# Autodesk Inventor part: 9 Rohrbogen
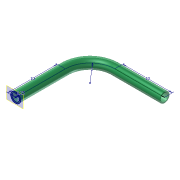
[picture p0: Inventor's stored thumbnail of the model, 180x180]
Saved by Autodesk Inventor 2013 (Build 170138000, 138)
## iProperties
Created: 2012-10
Part Number: 9 Rohrbogen
Material: Allgemein
Vendor: www.inventor-faq.de
Document SubType Name: Modeling
Designer: Administrator
Manufacturer: www.inventor-faq.de
Density: 1 g/cm^3
RuleStatus: InUse
AfterDocOpen0: inventorfaq
BeforeDocSave0: inventorfaq
Author: Administrator
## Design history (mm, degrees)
sketch "Skizze1"
  geometry: L1 (0, 0)-(0, 10); L2 (5.002, 15)-(15.002, 15); A1 r 5 centre (5, 10) between (5.002, 15) and (0, 10)
  constraints: 4 end point, 2 point on circle, 1 centre point, 1 perpendicular, 1 tangent, 1 vertical
  dimensions: "d0" = 10 distance of L1.start L1.end; "d1" = 10 distance of L2.start L2.end; "d2" = 5 radius of A1
sketch "Skizze2"
  geometry: C1 r 1 at (0, 0); C2 r 0.75 at (0, 0); 1 further point
  constraints: 2 centre point, 2 coincident
  dimensions: "d3" = 2 diameter of C1; "d4" = 0.25 radial gap between concentric circles of C1 C2
feature "Sweeping1" sketch "Skizze1", "Skizze2" dims "d5" = 0
node "Volumenkörper1"
